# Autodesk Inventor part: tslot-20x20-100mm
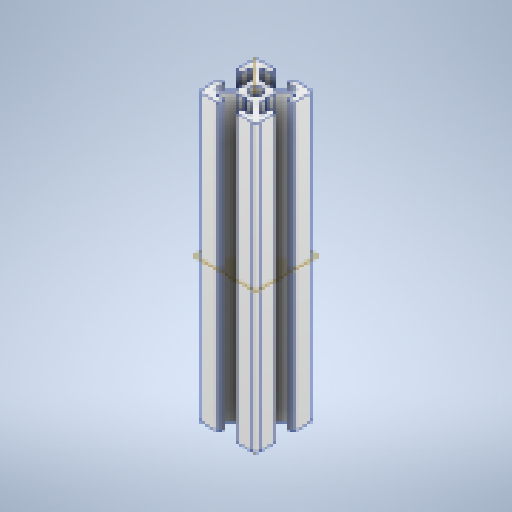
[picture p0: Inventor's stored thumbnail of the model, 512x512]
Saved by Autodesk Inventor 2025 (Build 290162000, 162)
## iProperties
Created: 2025-03
Part Number: tslot-20x20-100mm
Material: Alluminio 6061
Document SubType Name: Modeling
Designer: Ryzen5700u
Density: 2.7 g/cm^3
Appearance: Alluminio - Piatto
Author: Ryzen5700u
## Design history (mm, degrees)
feature "Base1"
sketch "Schizzo1"
  geometry: L1 (3.761, -16)-(4.7, -16) reference; L2 (3.761, -16)-(0.7, -12.939) reference; L3 (0.7, -12.939)-(0.7, -10.52) reference; L4 (0.4, -10)-(0.7, -10.52) reference; L5 (0.4, -10)-(0.7, -9.48) reference; L6 (0.7, -7.061)-(0.7, -9.48) reference; L7 (3.761, -4)-(0.7, -7.061) reference; L8 (3.761, -4)-(4.7, -4) reference; L9 (4.7, -4)-(4.7, -7) reference; L10 (4.7, -7)-(6.4, -7) reference; L11 (6.7, -6.7)-(6.7, -1) reference; L12 (5.7, 0)-(0, 0) reference; L13 (-0.3, -2)-(-0.3, -0.3) reference; L14 (2.7, -2)-(-0.3, -2) reference; L15 (2.7, -2.939)-(2.7, -2) reference; L16 (2.7, -2.939)-(-0.361, -6) reference; L17 (-0.361, -6)-(-2.78, -6) reference; L18 (-3.3, -6.3)-(-2.78, -6) reference; L19 (-3.3, -6.3)-(-3.82, -6) reference; L20 (-6.239, -6)-(-3.82, -6) reference; L21 (-9.3, -2.939)-(-6.239, -6) reference; L22 (-9.3, -2.939)-(-9.3, -2) reference; L23 (-9.3, -2)-(-6.3, -2) reference; L24 (-6.3, -2)-(-6.3, -0.3) reference; L25 (-12.3, 0)-(-6.6, 0) reference; L26 (-13.3, -6.7)-(-13.3, -1) reference; L27 (-11.3, -7)-(-13, -7) reference; L28 (-11.3, -4)-(-11.3, -7) reference; L29 (-10.361, -4)-(-11.3, -4) reference; L30 (-10.361, -4)-(-7.3, -7.061) reference; L31 (-7.3, -7.061)-(-7.3, -9.48) reference; L32 (-7, -10)-(-7.3, -9.48) reference; L33 (-7, -10)-(-7.3, -10.52) reference; L34 (-7.3, -12.939)-(-7.3, -10.52) reference; L35 (-10.361, -16)-(-7.3, -12.939) reference; L36 (-10.361, -16)-(-11.3, -16) reference; L37 (-11.3, -16)-(-11.3, -13) reference; L38 (-11.3, -13)-(-13, -13) reference; L39 (-13.3, -13.3)-(-13.3, -19) reference; L40 (-12.3, -20)-(-6.6, -20) reference; L41 (-6.3, -18)-(-6.3, -19.7) reference; L42 (-9.3, -18)-(-6.3, -18) reference; L43 (-9.3, -17.061)-(-9.3, -18) reference; L44 (-9.3, -17.061)-(-6.239, -14) reference; L45 (-6.239, -14)-(-3.82, -14) reference; L46 (-3.3, -13.7)-(-3.82, -14) reference; L47 (-3.3, -13.7)-(-2.78, -14) reference; L48 (-0.361, -14)-(-2.78, -14) reference; L49 (2.7, -17.061)-(-0.361, -14) reference; L50 (2.7, -17.061)-(2.7, -18) reference; L51 (2.7, -18)-(-0.3, -18) reference; L52 (-0.3, -18)-(-0.3, -19.7) reference; L53 (5.7, -20)-(0, -20) reference; L54 (6.7, -13.3)-(6.7, -19) reference; L55 (4.7, -13)-(6.4, -13) reference; L56 (4.7, -16)-(4.7, -13) reference; C1 r 2.1 at (-3.3, -10) reference; A1 r 0.3 centre (6.4, -6.7) between (6.4, -7) and (6.7, -6.7) reference; A2 r 1 centre (5.7, -1) between (6.7, -1) and (5.7, 0) reference; A3 r 0.3 centre (0, -0.3) between (0, 0) and (-0.3, -0.3) reference; A4 r 0.3 centre (-6.6, -0.3) between (-6.3, -0.3) and (-6.6, 0) reference; A5 r 1 centre (-12.3, -1) between (-12.3, 0) and (-13.3, -1) reference; A6 r 0.3 centre (-13, -6.7) between (-13.3, -6.7) and (-13, -7) reference; A7 r 0.3 centre (-13, -13.3) between (-13, -13) and (-13.3, -13.3) reference; A8 r 1 centre (-12.3, -19) between (-13.3, -19) and (-12.3, -20) reference; A9 r 0.3 centre (-6.6, -19.7) between (-6.6, -20) and (-6.3, -19.7) reference; A10 r 0.3 centre (0, -19.7) between (-0.3, -19.7) and (0, -20) reference; A11 r 1 centre (5.7, -19) between (5.7, -20) and (6.7, -19) reference; A12 r 0.3 centre (6.4, -13.3) between (6.7, -13.3) and (6.4, -13) reference; 1 further point
extrude "Estrusione1" join sketch "Schizzo1" distance "d0" = 90; taper "d1" = 0 deg
node "Piano di lavoro1"
node "Asse di lavoro1"
node "Solido1"
node "Linea chiusa proiettata1"
